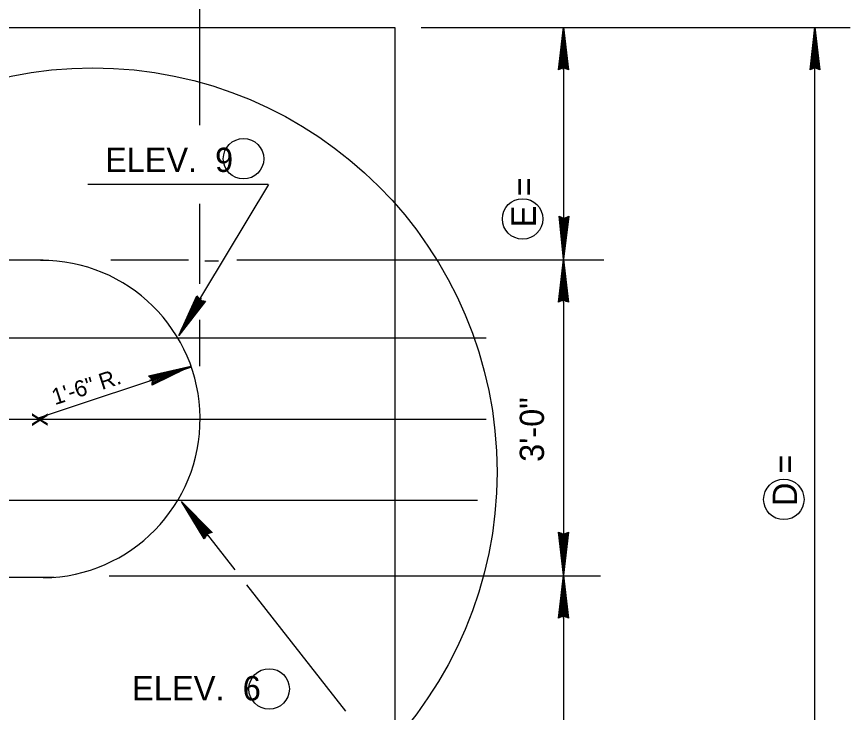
# Model space of a CAD drawing. Extents: x 1.6 to 6.29, y 2.8 to 7.08.
# Drawn here: x 3.4141 to 3.8411, y 6.3905 to 6.7469 of the extents above; entities that cross this region are included whole.
import ezdxf

# ---------------------------------------------------------------- set-up
doc = ezdxf.new("R2010")
doc.units = 0
doc.layers.add('Level 1', color=7, linetype='Continuous')
doc.layers.add('Level 5', color=7, linetype='Continuous')

msp = doc.modelspace()

# ---------------------------------------------------------------- linework, layer by layer
at = {"layer": 'Level 1'}
for p, q in [((3.50783, 6.69133), (3.50783, 6.86208)), ((2.80525, 6.74125), (3.60783, 6.74125)), ((3.60783, 6.74125), (3.60783, 6.33992)), ((3.62125, 6.74125), (3.84108, 6.74125)), ((3.69167, 6.71958), (3.69417, 6.74158)), ((3.69417, 6.71958), (3.69417, 6.74158)), ((3.69417, 6.74158), (3.69675, 6.71958)), ((3.69417, 6.74017), (3.69417, 6.34283)), ((3.69458, 6.73583), (3.69433, 6.73858)), ((3.69433, 6.73858), (3.69433, 6.72108)), ((3.82058, 6.71958), (3.82292, 6.74158)), ((3.82275, 6.741), (3.82275, 6.34175)), ((3.82292, 6.71958), (3.82292, 6.74158)), ((3.82292, 6.74158), (3.82542, 6.71958)), ((3.82333, 6.73583), (3.823, 6.73858)), ((3.823, 6.73858), (3.82325, 6.72108)), ((3.69217, 6.72), (3.69383, 6.73642)), ((3.69217, 6.72), (3.69392, 6.73642)), ((3.69233, 6.72), (3.694, 6.73642)), ((3.69242, 6.72), (3.69408, 6.73625)), ((3.69258, 6.72), (3.69433, 6.73625)), ((3.69358, 6.72817), (3.69408, 6.73792)), ((3.6955, 6.71992), (3.69392, 6.73508)), ((3.69408, 6.73792), (3.69458, 6.73583)), ((3.69583, 6.72), (3.69417, 6.73517)), ((3.696, 6.72), (3.69433, 6.73525)), ((3.69642, 6.72), (3.69458, 6.73525)), ((3.82092, 6.72), (3.82258, 6.73642)), ((3.82092, 6.72), (3.82267, 6.73642)), ((3.82092, 6.72), (3.82275, 6.73642)), ((3.82108, 6.72), (3.82283, 6.73625)), ((3.82125, 6.72), (3.823, 6.73625)), ((3.82233, 6.72817), (3.82283, 6.73792)), ((3.82433, 6.71992), (3.82267, 6.73508)), ((3.82283, 6.73792), (3.82333, 6.73583)), ((3.82467, 6.72), (3.82292, 6.73517)), ((3.82492, 6.72), (3.82325, 6.73525)), ((3.82508, 6.72), (3.82333, 6.73525)), ((3.69392, 6.72108), (3.69375, 6.73083)), ((3.69375, 6.73083), (3.69408, 6.73075)), ((3.69408, 6.73075), (3.69392, 6.729)), ((3.69467, 6.72083), (3.694, 6.73192)), ((3.694, 6.73192), (3.69508, 6.72067)), ((3.82267, 6.72108), (3.8225, 6.73083)), ((3.8225, 6.73083), (3.82283, 6.73075)), ((3.82283, 6.73075), (3.82267, 6.729)), ((3.82358, 6.72083), (3.82275, 6.73192)), ((3.82275, 6.73192), (3.82392, 6.72067)), ((3.69308, 6.72058), (3.69358, 6.72817)), ((3.69333, 6.72533), (3.69308, 6.72058)), ((3.69342, 6.72083), (3.69333, 6.72533)), ((3.69358, 6.72733), (3.69342, 6.72083)), ((3.69375, 6.72108), (3.69358, 6.72733)), ((3.69392, 6.729), (3.69375, 6.72108)), ((3.69433, 6.72108), (3.69467, 6.72617)), ((3.69467, 6.72617), (3.69467, 6.72083)), ((3.82192, 6.72058), (3.82233, 6.72817)), ((3.82208, 6.72533), (3.82192, 6.72058)), ((3.82225, 6.72083), (3.82208, 6.72533)), ((3.82233, 6.72733), (3.82225, 6.72083)), ((3.8225, 6.72108), (3.82233, 6.72733)), ((3.82267, 6.729), (3.8225, 6.72108)), ((3.82325, 6.72108), (3.82358, 6.72617)), ((3.82358, 6.72617), (3.82358, 6.72083)), ((3.694, 6.72117), (3.6925, 6.72017)), ((3.69342, 6.72158), (3.69275, 6.72133)), ((3.69275, 6.72133), (3.69425, 6.721)), ((3.69283, 6.72067), (3.69358, 6.72117)), ((3.69358, 6.72117), (3.69342, 6.72158)), ((3.69508, 6.72067), (3.694, 6.72117)), ((3.82275, 6.72117), (3.82117, 6.72017)), ((3.82225, 6.72158), (3.82142, 6.72133)), ((3.82142, 6.72133), (3.823, 6.721)), ((3.8215, 6.72067), (3.82233, 6.72117)), ((3.82233, 6.72117), (3.82225, 6.72158)), ((3.82392, 6.72067), (3.82275, 6.72117)), ((3.69417, 6.72075), (3.69167, 6.71958)), ((3.6925, 6.72017), (3.69283, 6.72067)), ((3.69675, 6.71958), (3.69417, 6.72075)), ((3.69425, 6.721), (3.69508, 6.72058)), ((3.69508, 6.72058), (3.69633, 6.72)), ((3.82292, 6.72075), (3.82058, 6.71958)), ((3.82117, 6.72017), (3.8215, 6.72067)), ((3.82542, 6.71958), (3.82292, 6.72075)), ((3.823, 6.721), (3.82392, 6.72058)), ((3.82392, 6.72058), (3.825, 6.72)), ((3.4505, 6.661), (3.54283, 6.661)), ((3.543, 6.66092), (3.49917, 6.58792)), ((3.50783, 6.61008), (3.50783, 6.65092)), ((3.69425, 6.62267), (3.692, 6.64467)), ((3.692, 6.64467), (3.69433, 6.64342)), ((3.69233, 6.64425), (3.69392, 6.62883)), ((3.69333, 6.64367), (3.69233, 6.64425)), ((3.6925, 6.64425), (3.69408, 6.62883)), ((3.69275, 6.64425), (3.69433, 6.629)), ((3.693, 6.64425), (3.69458, 6.629)), ((3.69425, 6.64467), (3.69425, 6.62267)), ((3.69683, 6.64467), (3.69425, 6.62267)), ((3.69592, 6.64425), (3.69425, 6.62783)), ((3.69433, 6.64342), (3.69683, 6.64467)), ((3.69633, 6.64425), (3.69433, 6.62783)), ((3.69658, 6.64425), (3.69458, 6.62775)), ((3.6965, 6.64425), (3.69458, 6.62775)), ((3.69642, 6.64425), (3.69458, 6.62775)), ((3.69425, 6.64325), (3.69333, 6.64367)), ((3.69458, 6.63217), (3.69333, 6.64358)), ((3.69333, 6.64358), (3.69458, 6.64308)), ((3.69375, 6.638), (3.69375, 6.64342)), ((3.69375, 6.64342), (3.69458, 6.63217)), ((3.69408, 6.64308), (3.69375, 6.638)), ((3.69417, 6.62567), (3.69408, 6.64308)), ((3.69583, 6.64292), (3.69425, 6.64325)), ((3.69458, 6.64308), (3.696, 6.64408)), ((3.69458, 6.64308), (3.69458, 6.63333)), ((3.69458, 6.63525), (3.69458, 6.64308)), ((3.69458, 6.64308), (3.69492, 6.63675)), ((3.69533, 6.64358), (3.69483, 6.63608)), ((3.69567, 6.64358), (3.69483, 6.64308)), ((3.69483, 6.64308), (3.695, 6.6425)), ((3.69492, 6.63675), (3.69492, 6.64342)), ((3.69492, 6.64342), (3.69508, 6.63883)), ((3.695, 6.6425), (3.69583, 6.64292)), ((3.69508, 6.63883), (3.69533, 6.64358)), ((3.696, 6.64408), (3.69567, 6.64358)), ((3.69483, 6.63608), (3.69433, 6.62633)), ((3.69433, 6.63342), (3.69458, 6.63525)), ((3.69458, 6.63333), (3.69433, 6.63342)), ((3.69433, 6.62633), (3.69392, 6.62842)), ((3.69392, 6.62842), (3.69417, 6.62567)), ((2.90658, 6.62233), (3.42758, 6.62233)), ((3.46233, 6.62233), (3.50208, 6.62233)), ((3.5105, 6.62175), (3.5175, 6.62175)), ((3.52692, 6.62233), (3.71483, 6.62233)), ((3.69167, 6.60058), (3.69417, 6.6225)), ((3.69358, 6.60908), (3.69408, 6.61892)), ((3.69408, 6.61892), (3.69458, 6.61683)), ((3.69417, 6.60058), (3.69417, 6.6225)), ((3.69417, 6.6225), (3.69675, 6.60058)), ((3.69458, 6.61683), (3.69433, 6.6195)), ((3.69433, 6.6195), (3.69433, 6.60208)), ((3.69217, 6.60108), (3.69383, 6.61742)), ((3.69217, 6.60092), (3.69392, 6.61742)), ((3.69233, 6.60092), (3.694, 6.61742)), ((3.69242, 6.60092), (3.69408, 6.61733)), ((3.69258, 6.60092), (3.69433, 6.61733)), ((3.6955, 6.60083), (3.69392, 6.61617)), ((3.69583, 6.60092), (3.69417, 6.61625)), ((3.696, 6.60092), (3.69433, 6.61642)), ((3.69642, 6.60108), (3.69458, 6.61642)), ((3.69392, 6.60208), (3.69375, 6.61183)), ((3.69375, 6.61183), (3.69408, 6.61175)), ((3.69408, 6.61175), (3.69392, 6.60992)), ((3.69467, 6.60183), (3.694, 6.61308)), ((3.694, 6.61308), (3.69508, 6.60167)), ((3.69308, 6.60158), (3.69358, 6.60908)), ((3.69333, 6.60642), (3.69308, 6.60158)), ((3.69342, 6.60183), (3.69333, 6.60642)), ((3.69358, 6.60842), (3.69342, 6.60183)), ((3.69375, 6.60208), (3.69358, 6.60842)), ((3.69392, 6.60992), (3.69375, 6.60208)), ((3.69433, 6.60208), (3.69467, 6.60725)), ((3.69467, 6.60725), (3.69467, 6.60183)), ((3.49708, 6.58358), (3.50633, 6.60383)), ((3.5085, 6.60267), (3.49708, 6.58358)), ((3.50658, 6.60333), (3.49992, 6.58933)), ((3.50667, 6.60325), (3.5, 6.58917)), ((3.50683, 6.60317), (3.50025, 6.58892)), ((3.50708, 6.60317), (3.50058, 6.58892)), ((3.50233, 6.59183), (3.50717, 6.60217)), ((3.5075, 6.60175), (3.50233, 6.59183)), ((3.50467, 6.59717), (3.5075, 6.60175)), ((3.50633, 6.60383), (3.50783, 6.60158)), ((3.50717, 6.60233), (3.50642, 6.60325)), ((3.50767, 6.6015), (3.50717, 6.60233)), ((3.50717, 6.60217), (3.50783, 6.60108)), ((3.50892, 6.60033), (3.50767, 6.6015)), ((3.50783, 6.60158), (3.51075, 6.60117)), ((3.69417, 6.60175), (3.69167, 6.60058)), ((3.694, 6.60217), (3.6925, 6.60108)), ((3.6925, 6.60108), (3.69283, 6.60167)), ((3.69342, 6.60267), (3.69275, 6.60233)), ((3.69275, 6.60233), (3.69425, 6.60192)), ((3.69283, 6.60167), (3.69358, 6.60217)), ((3.69358, 6.60217), (3.69342, 6.60267)), ((3.69508, 6.60167), (3.694, 6.60217)), ((3.69675, 6.60058), (3.69417, 6.60175)), ((3.69425, 6.60192), (3.69508, 6.60158)), ((3.69508, 6.60158), (3.69633, 6.60108)), ((3.51075, 6.60117), (3.49708, 6.58358)), ((3.49842, 6.58633), (3.50758, 6.60125)), ((3.50983, 6.60142), (3.49958, 6.58808)), ((3.51017, 6.60117), (3.49967, 6.58792)), ((3.51, 6.60125), (3.49983, 6.58792)), ((3.51017, 6.60108), (3.49992, 6.58792)), ((3.51, 6.60092), (3.5, 6.58792)), ((3.50783, 6.60108), (3.503, 6.59258)), ((3.50383, 6.59442), (3.50817, 6.60108)), ((3.509, 6.60117), (3.50458, 6.59492)), ((3.50758, 6.60125), (3.50467, 6.59717)), ((3.50817, 6.60108), (3.50492, 6.59533)), ((3.50492, 6.59533), (3.5085, 6.60108)), ((3.50625, 6.59717), (3.509, 6.60117)), ((3.5085, 6.60108), (3.50625, 6.59717)), ((3.50783, 6.60108), (3.50983, 6.60108)), ((3.50825, 6.60083), (3.50808, 6.60033)), ((3.50808, 6.60033), (3.50892, 6.60033)), ((3.50917, 6.60083), (3.50825, 6.60083)), ((3.50983, 6.60108), (3.50917, 6.60083)), ((3.50458, 6.59492), (3.49908, 6.58675)), ((3.50283, 6.59275), (3.50383, 6.59442)), ((3.49958, 6.58867), (3.49842, 6.58633)), ((3.49908, 6.58675), (3.49958, 6.58867)), ((3.503, 6.59258), (3.50283, 6.59275)), ((3.50783, 6.56775), (3.50783, 6.5915)), ((2.71542, 6.58242), (3.6545, 6.58242)), ((3.42483, 6.54117), (3.50325, 6.56733)), ((3.48167, 6.56292), (3.50333, 6.56783)), ((3.48233, 6.56058), (3.50333, 6.56783)), ((3.50333, 6.56783), (3.48342, 6.55808)), ((3.482, 6.56258), (3.49858, 6.56608)), ((3.48208, 6.56258), (3.49842, 6.56608)), ((3.48208, 6.56233), (3.49842, 6.56608)), ((3.48225, 6.56258), (3.49833, 6.56633)), ((3.48233, 6.56225), (3.49858, 6.566)), ((3.48275, 6.56192), (3.49033, 6.56408)), ((3.48767, 6.56333), (3.48275, 6.56192)), ((3.48983, 6.56383), (3.48325, 6.56158)), ((3.48325, 6.56158), (3.48767, 6.56333)), ((3.48333, 6.55933), (3.49725, 6.56583)), ((3.48342, 6.55917), (3.49767, 6.56575)), ((3.48342, 6.55908), (3.49758, 6.5655)), ((3.48358, 6.55858), (3.49758, 6.56517)), ((3.49408, 6.56483), (3.48367, 6.56008)), ((3.49117, 6.56408), (3.48367, 6.5615)), ((3.48367, 6.5615), (3.48983, 6.56383)), ((3.48383, 6.56058), (3.49408, 6.56483)), ((3.50067, 6.56658), (3.484, 6.56083)), ((3.484, 6.56117), (3.49317, 6.56467)), ((3.49033, 6.56408), (3.49983, 6.56658)), ((3.49333, 6.5645), (3.49117, 6.56408)), ((3.49317, 6.56467), (3.49333, 6.5645)), ((3.49983, 6.56658), (3.49808, 6.5655)), ((3.49808, 6.5655), (3.50067, 6.56658)), ((3.48358, 6.56083), (3.48167, 6.56292)), ((3.484, 6.56108), (3.48233, 6.56242)), ((3.48233, 6.56242), (3.483, 6.56208)), ((3.483, 6.56208), (3.48367, 6.56167)), ((3.48342, 6.55808), (3.48358, 6.56083)), ((3.48367, 6.56083), (3.48358, 6.55992)), ((3.48358, 6.55992), (3.48367, 6.55892)), ((3.48433, 6.562), (3.48367, 6.56242)), ((3.48367, 6.56242), (3.48367, 6.56083)), ((3.48367, 6.56167), (3.48433, 6.562)), ((3.48367, 6.56008), (3.484, 6.56108)), ((3.48883, 6.56225), (3.48383, 6.56058)), ((3.484, 6.56083), (3.48883, 6.56225)), ((3.20508, 6.54075), (3.6545, 6.54075)), ((2.7135, 6.49917), (3.65008, 6.49917)), ((3.51217, 6.481), (3.49858, 6.49842)), ((3.51017, 6.47942), (3.49858, 6.49842)), ((3.49858, 6.49842), (3.51417, 6.48258)), ((3.52608, 6.46342), (3.49917, 6.49775)), ((3.50242, 6.49425), (3.5005, 6.49617)), ((3.5005, 6.49617), (3.51133, 6.48242)), ((3.50642, 6.48742), (3.50067, 6.4955)), ((3.50067, 6.4955), (3.50242, 6.49425)), ((3.51025, 6.47992), (3.50158, 6.49417)), ((3.51025, 6.48008), (3.50158, 6.49408)), ((3.51033, 6.47992), (3.50167, 6.49433)), ((3.5105, 6.48008), (3.50167, 6.49425)), ((3.51067, 6.48017), (3.50192, 6.49442)), ((3.51317, 6.48217), (3.50233, 6.49317)), ((3.51325, 6.48242), (3.50242, 6.4935)), ((3.51342, 6.48258), (3.50267, 6.49367)), ((3.5135, 6.48258), (3.50283, 6.49367)), ((3.51183, 6.48217), (3.50442, 6.49067)), ((3.50442, 6.49067), (3.51233, 6.48242)), ((3.51108, 6.482), (3.50492, 6.48975)), ((3.50492, 6.48975), (3.50517, 6.48975)), ((3.50517, 6.48975), (3.50625, 6.48817)), ((3.50625, 6.48817), (3.511, 6.48175)), ((3.51083, 6.481), (3.50642, 6.48742)), ((3.511, 6.48175), (3.50675, 6.48683)), ((3.50675, 6.48683), (3.51092, 6.4815)), ((3.51133, 6.48242), (3.50842, 6.4865)), ((3.50842, 6.4865), (3.51183, 6.48217)), ((3.51092, 6.4815), (3.50783, 6.48508)), ((3.50783, 6.48508), (3.51083, 6.481)), ((3.51025, 6.48208), (3.51, 6.48142)), ((3.51, 6.48142), (3.5115, 6.48208)), ((3.51158, 6.48192), (3.51017, 6.47942)), ((3.51075, 6.48175), (3.51025, 6.48208)), ((3.51117, 6.48208), (3.5105, 6.48025)), ((3.51233, 6.48242), (3.51117, 6.48208)), ((3.5115, 6.48208), (3.51242, 6.48242)), ((3.51417, 6.48258), (3.51158, 6.48192)), ((3.51242, 6.48242), (3.51342, 6.48275)), ((3.69417, 6.46083), (3.69167, 6.48283)), ((3.69167, 6.48283), (3.69425, 6.48175)), ((3.69217, 6.4825), (3.69383, 6.46717)), ((3.69325, 6.48192), (3.69233, 6.4825)), ((3.69242, 6.4825), (3.694, 6.46717)), ((3.69267, 6.4825), (3.69425, 6.46717)), ((3.69292, 6.4825), (3.69458, 6.46725)), ((3.69417, 6.4815), (3.69325, 6.48192)), ((3.69417, 6.48283), (3.69417, 6.46083)), ((3.69675, 6.48283), (3.69417, 6.46083)), ((3.69592, 6.4825), (3.69417, 6.46617)), ((3.69425, 6.48175), (3.69675, 6.48283)), ((3.696, 6.4825), (3.69425, 6.46617)), ((3.69633, 6.4825), (3.6945, 6.46608)), ((3.6945, 6.48125), (3.69592, 6.48225)), ((3.6965, 6.4825), (3.69458, 6.46608)), ((3.69642, 6.4825), (3.69458, 6.46608)), ((3.69592, 6.48225), (3.69567, 6.48175)), ((3.51033, 6.481), (3.51075, 6.48175)), ((3.5105, 6.48025), (3.51033, 6.481)), ((3.6945, 6.4705), (3.69325, 6.48175)), ((3.69325, 6.48175), (3.6945, 6.48125)), ((3.69367, 6.47625), (3.69367, 6.48175)), ((3.69367, 6.48175), (3.6945, 6.4705)), ((3.694, 6.48142), (3.69367, 6.47625)), ((3.69408, 6.46392), (3.694, 6.48142)), ((3.69567, 6.48117), (3.69417, 6.4815)), ((3.69458, 6.48142), (3.69458, 6.47158)), ((3.69458, 6.4735), (3.69458, 6.48142)), ((3.69458, 6.48142), (3.69483, 6.47517)), ((3.69525, 6.48183), (3.69483, 6.47433)), ((3.69483, 6.47517), (3.69483, 6.48175)), ((3.69483, 6.48175), (3.695, 6.47708)), ((3.69567, 6.48175), (3.69483, 6.48125)), ((3.69483, 6.48125), (3.69492, 6.48075)), ((3.69492, 6.48075), (3.69567, 6.48117)), ((3.695, 6.47708), (3.69525, 6.48183)), ((3.69483, 6.47433), (3.69433, 6.4645)), ((3.69433, 6.47167), (3.69458, 6.4735)), ((3.69458, 6.47158), (3.69433, 6.47167)), ((3.69433, 6.4645), (3.69383, 6.46667)), ((3.69383, 6.46667), (3.69408, 6.46392)), ((3.69167, 6.43875), (3.69417, 6.46067)), ((3.69417, 6.43875), (3.69417, 6.46067)), ((3.69417, 6.46067), (3.69675, 6.43875)), ((2.90658, 6.45975), (3.43333, 6.45975)), ((3.4615, 6.4605), (3.71317, 6.4605)), ((3.69358, 6.44725), (3.69408, 6.45717)), ((3.69408, 6.45717), (3.69458, 6.455)), ((3.69458, 6.455), (3.69433, 6.45775)), ((3.69433, 6.45775), (3.69433, 6.44033)), ((3.58275, 6.39108), (3.532, 6.45583)), ((3.69217, 6.43925), (3.69383, 6.45558)), ((3.69217, 6.43908), (3.69392, 6.45558)), ((3.69233, 6.43908), (3.694, 6.45558)), ((3.69242, 6.43908), (3.69408, 6.4555)), ((3.69258, 6.43908), (3.69433, 6.4555)), ((3.6955, 6.439), (3.69392, 6.45433)), ((3.69583, 6.43908), (3.69417, 6.45442)), ((3.696, 6.43908), (3.69433, 6.4545)), ((3.69642, 6.43925), (3.69458, 6.4545)), ((3.69392, 6.44033), (3.69375, 6.45)), ((3.69375, 6.45), (3.69408, 6.44992)), ((3.69392, 6.448), (3.69375, 6.44033)), ((3.69408, 6.44992), (3.69392, 6.448)), ((3.69467, 6.44008), (3.694, 6.45125)), ((3.694, 6.45125), (3.69508, 6.43992)), ((3.69308, 6.43983), (3.69358, 6.44725)), ((3.69333, 6.44467), (3.69308, 6.43983)), ((3.69342, 6.44008), (3.69333, 6.44467)), ((3.69358, 6.44658), (3.69342, 6.44008)), ((3.69375, 6.44033), (3.69358, 6.44658)), ((3.69433, 6.44033), (3.69467, 6.44542)), ((3.69467, 6.44542), (3.69467, 6.44008)), ((3.69417, 6.44), (3.69167, 6.43875)), ((3.694, 6.44042), (3.6925, 6.43925)), ((3.6925, 6.43925), (3.69283, 6.43992)), ((3.69342, 6.44083), (3.69275, 6.4405)), ((3.69275, 6.4405), (3.69425, 6.44017)), ((3.69283, 6.43992), (3.69358, 6.44042)), ((3.69358, 6.44042), (3.69342, 6.44083)), ((3.69508, 6.43992), (3.694, 6.44042)), ((3.69675, 6.43875), (3.69417, 6.44)), ((3.69425, 6.44017), (3.69508, 6.43983)), ((3.69508, 6.43983), (3.69633, 6.43925))]:
    msp.add_line(p, q, dxfattribs=at)
for centre, radius in [((3.45306, 6.51361), 0.20706), ((3.53029, 6.67409), 0.01036), ((3.67322, 6.64325), 0.01036), ((3.80703, 6.49957), 0.01036), ((3.54339, 6.40249), 0.01036)]:
    msp.add_circle(centre, radius, dxfattribs=at)
msp.add_arc((3.4267, 6.54072), 0.08133, 270.8201, 90.2329, dxfattribs=at)

# ---------------------------------------------------------------- texts
for s, height, rotation, p in [('1\'-6" R.', 0.008333, 17.8927, (3.43367, 6.54783)), ('3\'-0"', 0.012417, 90, (3.68417, 6.51883)), ('x', 0.01042, 270, (3.42192, 6.54392))]:
    msp.add_text(s, height=height, rotation=rotation, dxfattribs=at).set_placement(p)
at = {"layer": 'Level 5'}
for s, height, p in [('ELEV.  9', 0.012416, (3.45942, 6.66733)), ('ELEV.  6', 0.0125, (3.47317, 6.39658))]:
    msp.add_text(s, height=height, dxfattribs=at).set_placement(p)
for s, height, p in [('E =      ', 0.0125, (3.68, 6.639)), ('D =      ', 0.012417, (3.81375, 6.49617))]:
    msp.add_text(s, height=height, rotation=90, dxfattribs=at).set_placement(p)

doc.saveas('drawing.dxf')
